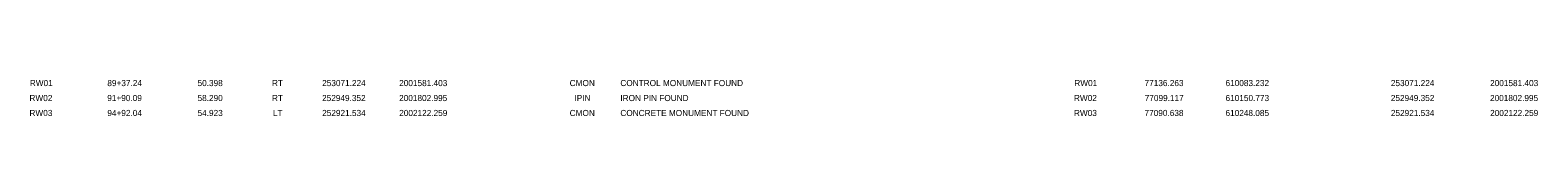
# Model space of a CAD drawing. Extents: x -4451 to 6119, y -1533 to 848.
# Drawn here: x -569 to -40, y 263 to 275 of the extents above; entities that cross this region are included whole.
import ezdxf

# ---------------------------------------------------------------- set-up
doc = ezdxf.new("R2010")
doc.units = 0
doc.layers.add('SC_Scratch1', color=7, linetype='Continuous')

msp = doc.modelspace()

# ---------------------------------------------------------------- texts
at = {"layer": 'SC_Scratch1'}
for s, p in [('RW01', (-568.72, 273.15)), ('RW01', (-568.72, 273.15)), ('RW01', (-568.72, 273.15)), ('RW01', (-568.72, 273.15)), ('89+37.24', (-541.55, 273.15)), ('89+37.24', (-541.55, 273.15)), ('89+37.24', (-541.55, 273.15)), ('89+37.24', (-541.55, 273.15)), ('50.398', (-509.94, 273.15)), ('50.398', (-509.94, 273.15)), ('50.398', (-509.94, 273.15)), ('50.398', (-509.94, 273.15)), ('RT', (-483.84, 273.15)), ('RT', (-483.84, 273.15)), ('RT', (-483.84, 273.15)), ('RT', (-483.84, 273.15)), ('253071.224', (-466.25, 273.15)), ('253071.224', (-466.25, 273.15)), ('253071.224', (-466.25, 273.15)), ('253071.224', (-466.25, 273.15)), ('2001581.403', (-439.26, 273.15)), ('2001581.403', (-439.26, 273.15)), ('2001581.403', (-439.26, 273.15)), ('2001581.403', (-439.26, 273.15)), ('CMON', (-379.5, 273.15)), ('CMON', (-379.5, 273.15)), ('CMON', (-379.5, 273.15)), ('CMON', (-379.5, 273.15)), ('CONTROL MONUMENT FOUND', (-361.73, 273.15)), ('CONTROL MONUMENT FOUND', (-361.73, 273.15)), ('CONTROL MONUMENT FOUND', (-361.73, 273.15)), ('CONTROL MONUMENT FOUND', (-361.73, 273.15)), ('RW01', (-202.61, 273.15)), ('RW01', (-202.61, 273.15)), ('RW01', (-202.61, 273.15)), ('RW01', (-202.61, 273.15)), ('77136.263', (-177.99, 273.15)), ('77136.263', (-177.99, 273.15)), ('77136.263', (-177.99, 273.15)), ('77136.263', (-177.99, 273.15)), ('610083.232', (-149.61, 273.15)), ('610083.232', (-149.61, 273.15)), ('610083.232', (-149.61, 273.15)), ('610083.232', (-149.61, 273.15)), ('253071.224', (-91.66, 273.15)), ('253071.224', (-91.66, 273.15)), ('253071.224', (-91.66, 273.15)), ('253071.224', (-91.66, 273.15)), ('2001581.403', (-56.88, 273.15)), ('2001581.403', (-56.88, 273.15)), ('2001581.403', (-56.88, 273.15)), ('2001581.403', (-56.88, 273.15)), ('RW02', (-568.84, 267.9)), ('RW02', (-568.84, 267.9)), ('RW02', (-568.84, 267.9)), ('RW02', (-568.84, 267.9)), ('91+90.09', (-541.57, 267.9)), ('91+90.09', (-541.57, 267.9)), ('91+90.09', (-541.57, 267.9)), ('91+90.09', (-541.57, 267.9)), ('58.290', (-509.94, 267.9)), ('58.290', (-509.94, 267.9)), ('58.290', (-509.94, 267.9)), ('58.290', (-509.94, 267.9)), ('RT', (-483.84, 267.9)), ('RT', (-483.84, 267.9)), ('RT', (-483.84, 267.9)), ('RT', (-483.84, 267.9)), ('252949.352', (-466.28, 267.9)), ('252949.352', (-466.28, 267.9)), ('252949.352', (-466.28, 267.9)), ('252949.352', (-466.28, 267.9)), ('2001802.995', (-439.28, 267.9)), ('2001802.995', (-439.28, 267.9)), ('2001802.995', (-439.28, 267.9)), ('2001802.995', (-439.28, 267.9)), ('IPIN', (-377.82, 267.9)), ('IPIN', (-377.82, 267.9)), ('IPIN', (-377.82, 267.9)), ('IPIN', (-377.82, 267.9)), ('IRON PIN FOUND ', (-361.73, 267.9)), ('IRON PIN FOUND ', (-361.73, 267.9)), ('IRON PIN FOUND ', (-361.73, 267.9)), ('IRON PIN FOUND ', (-361.73, 267.9)), ('RW02', (-202.74, 267.9)), ('RW02', (-202.74, 267.9)), ('RW02', (-202.74, 267.9)), ('RW02', (-202.74, 267.9)), ('77099.117', (-177.93, 267.9)), ('77099.117', (-177.93, 267.9)), ('77099.117', (-177.93, 267.9)), ('77099.117', (-177.93, 267.9)), ('610150.773', (-149.6, 267.9)), ('610150.773', (-149.6, 267.9)), ('610150.773', (-149.6, 267.9)), ('610150.773', (-149.6, 267.9)), ('252949.352', (-91.68, 267.9)), ('252949.352', (-91.68, 267.9)), ('252949.352', (-91.68, 267.9)), ('252949.352', (-91.68, 267.9)), ('2001802.995', (-56.91, 267.9)), ('2001802.995', (-56.91, 267.9)), ('2001802.995', (-56.91, 267.9)), ('2001802.995', (-56.91, 267.9)), ('RW03', (-568.84, 262.65)), ('RW03', (-568.84, 262.65)), ('RW03', (-568.84, 262.65)), ('RW03', (-568.84, 262.65)), ('94+92.04', (-541.55, 262.65)), ('94+92.04', (-541.55, 262.65)), ('94+92.04', (-541.55, 262.65)), ('94+92.04', (-541.55, 262.65)), ('54.923', (-509.93, 262.65)), ('54.923', (-509.93, 262.65)), ('54.923', (-509.93, 262.65)), ('54.923', (-509.93, 262.65)), ('LT', (-483.5, 262.65)), ('LT', (-483.5, 262.65)), ('LT', (-483.5, 262.65)), ('LT', (-483.5, 262.65)), ('252921.534', (-466.25, 262.65)), ('252921.534', (-466.25, 262.65)), ('252921.534', (-466.25, 262.65)), ('252921.534', (-466.25, 262.65)), ('2002122.259', (-439.25, 262.65)), ('2002122.259', (-439.25, 262.65)), ('2002122.259', (-439.25, 262.65)), ('2002122.259', (-439.25, 262.65)), ('CMON', (-379.5, 262.65)), ('CMON', (-379.5, 262.65)), ('CMON', (-379.5, 262.65)), ('CMON', (-379.5, 262.65)), ('CONCRETE MONUMENT FOUND', (-361.73, 262.65)), ('CONCRETE MONUMENT FOUND', (-361.73, 262.65)), ('CONCRETE MONUMENT FOUND', (-361.73, 262.65)), ('CONCRETE MONUMENT FOUND', (-361.73, 262.65)), ('RW03', (-202.73, 262.65)), ('RW03', (-202.73, 262.65)), ('RW03', (-202.73, 262.65)), ('RW03', (-202.73, 262.65)), ('77090.638', (-178, 262.65)), ('77090.638', (-178, 262.65)), ('77090.638', (-178, 262.65)), ('77090.638', (-178, 262.65)), ('610248.085', (-149.62, 262.65)), ('610248.085', (-149.62, 262.65)), ('610248.085', (-149.62, 262.65)), ('610248.085', (-149.62, 262.65)), ('252921.534', (-91.66, 262.65)), ('252921.534', (-91.66, 262.65)), ('252921.534', (-91.66, 262.65)), ('252921.534', (-91.66, 262.65)), ('2002122.259', (-56.87, 262.65)), ('2002122.259', (-56.87, 262.65)), ('2002122.259', (-56.87, 262.65)), ('2002122.259', (-56.87, 262.65))]:
    msp.add_text(s, height=2.16, dxfattribs=at).set_placement(p)

doc.saveas('drawing.dxf')
